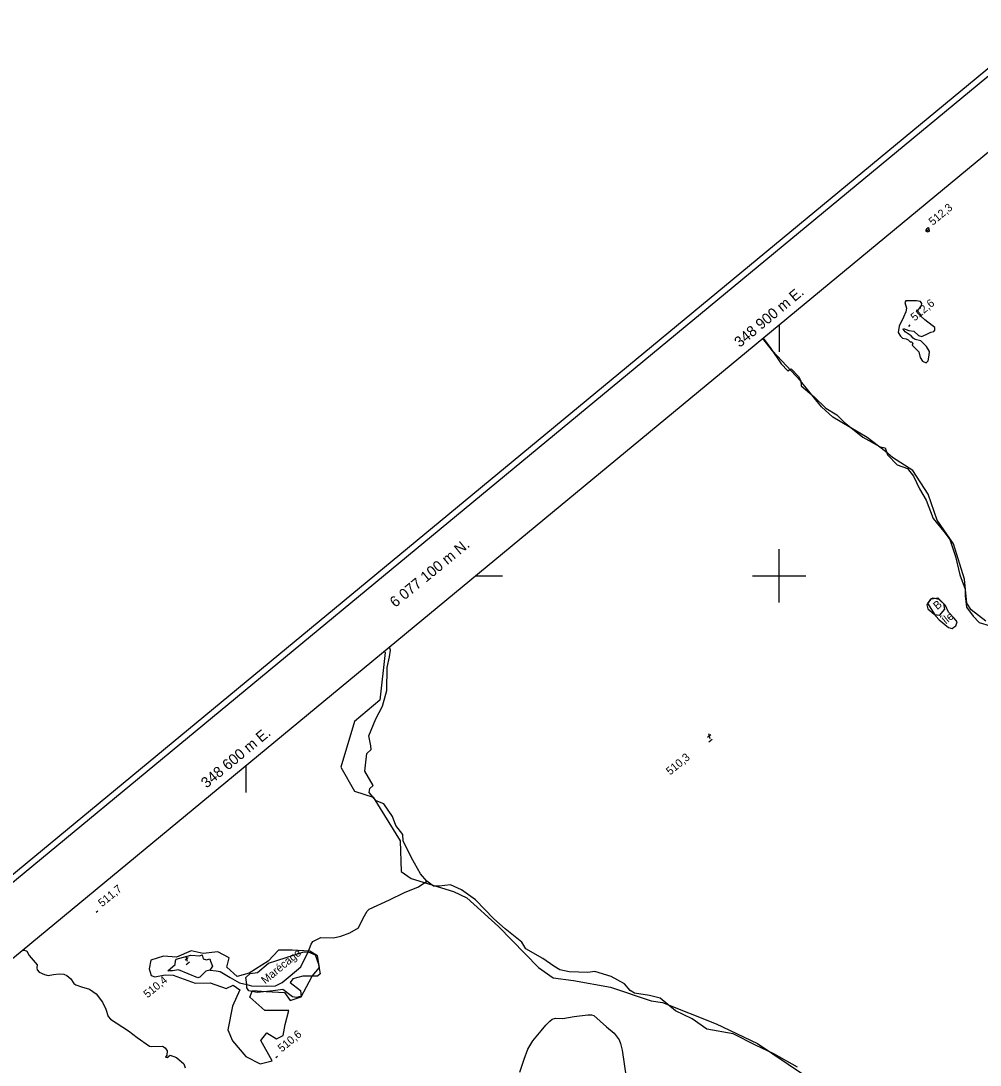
# Model space of a CAD drawing. Extents: x 347059 to 352153, y 6073752 to 6078601.
# Drawn here: x 348473 to 349013, y 6076825 to 6077412 of the extents above; entities that cross this region are included whole.
import ezdxf

# ---------------------------------------------------------------- set-up
doc = ezdxf.new("R2010")
doc.units = 0
for name, color, linetype in [('Level 1', 7, 'Continuous'), ('Level 2', 7, 'Continuous'), ('Level 22', 7, 'Continuous'), ('Level 3', 7, 'Continuous'), ('Level 4', 7, 'Continuous'), ('Level 44', 7, 'Continuous'), ('Level 60', 7, 'Continuous'), ('Level 61', 7, 'Continuous'), ('Level 7', 7, 'Continuous'), ('Level 8', 7, 'Continuous')]:
    doc.layers.add(name, color=color, linetype=linetype)

msp = doc.modelspace()

# ---------------------------------------------------------------- linework, layer by layer
at = {"layer": 'Level 1'}
msp.add_lwpolyline([(348474.58, 6076889.45), (348475.52, 6076889.34), (348476.87, 6076888.89), (348478.22, 6076886.38), (348481.5, 6076882.44), (348482.72, 6076881.18), (348482.51, 6076879.37), (348482.66, 6076878.42), (348483.81, 6076877.1), (348486.7, 6076875.8), (348488.85, 6076875.21), (348491.88, 6076875.66), (348494.98, 6076876.17), (348497.59, 6076875.85), (348499.29, 6076875.14), (348501.49, 6076873.24), (348503.19, 6076870.64), (348504.3, 6076869.83), (348507.51, 6076868.81), (348512.09, 6076867.47), (348515.81, 6076864.81), (348519.38, 6076860.1), (348521.22, 6076856.17), (348522.49, 6076852.15), (348523.83, 6076850.6), (348534.01, 6076844.05), (348538.92, 6076840.28), (348545.9, 6076835.43), (348547.1, 6076835.12), (348553.19, 6076835.35), (348554.7, 6076834.5), (348555.78, 6076832.74), (348555.59, 6076830.43), (348554.84, 6076829.26), (348555.76, 6076828.97), (348557.53, 6076830.35), (348561.11, 6076829.11), (348565.06, 6076825.37), (348565.86, 6076823.22)], dxfattribs=at)
at = {"layer": 'Level 2'}
for points in [[(348982.46, 6077293.93), (348983.6, 6077293.37), (348984.58, 6077293.81), (348984.42, 6077295.27), (348983.97, 6077295.64), (348982.88, 6077294.96), (348982.46, 6077293.93)], [(348975.85, 6077228.81), (348978.66, 6077225.97), (348979.4, 6077222.82), (348980.76, 6077220.72), (348982.83, 6077219.67), (348983.88, 6077220.84), (348984.5, 6077224.07), (348984.69, 6077226.19), (348982.98, 6077228.98), (348979.75, 6077232.15), (348976.64, 6077232.93), (348975.47, 6077233.61), (348974.4, 6077234.9), (348970.97, 6077237.23), (348969.91, 6077238.6), (348969.96, 6077239.09), (348972.96, 6077237.91), (348975.91, 6077237.6), (348978.51, 6077235.1), (348980.34, 6077234.6), (348983.88, 6077236.21), (348985.47, 6077237.01), (348987.01, 6077237.32), (348987.62, 6077238.21), (348987.58, 6077239.53), (348986.14, 6077240.81), (348981.93, 6077243.99), (348979.71, 6077246.04), (348977.91, 6077247.85), (348977.64, 6077248.53), (348980.08, 6077251.93), (348980.34, 6077253.05), (348979.5, 6077254.16), (348977.38, 6077254.64), (348973.94, 6077254.63), (348971.36, 6077254.58), (348970.84, 6077253.76), (348971.68, 6077250.4), (348971.3, 6077248.42), (348970.05, 6077245.49), (348967.5, 6077240.43), (348967.05, 6077236.81), (348968.26, 6077234.81), (348969.42, 6077233.59), (348971.59, 6077233.23), (348972.65, 6077232.68), (348973.8, 6077231.47), (348974.55, 6077231.56), (348975.18, 6077230.8), (348974.95, 6077229.72), (348975.85, 6077228.81)]]:
    msp.add_lwpolyline(points, dxfattribs=at)
at = {"layer": 'Level 22'}
msp.add_lwpolyline([(348754.11, 6076820.73), (348756.65, 6076828.11), (348758.66, 6076833.62), (348761.5, 6076838.4), (348766.13, 6076844), (348768.78, 6076847.12), (348771, 6076849.5), (348772.41, 6076850.61), (348774.17, 6076851.1), (348778.42, 6076851.05), (348784.66, 6076852.13), (348792.43, 6076853.07), (348794.47, 6076852.96), (348795.75, 6076852.6), (348802.86, 6076846.23), (348807.33, 6076842.67), (348810.02, 6076838.9), (348810.87, 6076836.98), (348811.83, 6076833.21), (348814.04, 6076817.7)], dxfattribs=at)
at = {"layer": 'Level 3'}
for p, q in [((348983.09, 6077294.04), (348984.01, 6077294.81)), ((348972.93, 6077240.27), (348973.85, 6077241.04)), ((348859.79, 6077009.14), (348861.6, 6077010.63)), ((348860.25, 6077011.27), (348861.08, 6077008.52)), ((348860.51, 6077006.62), (348862.36, 6077008.15)), ((348515.83, 6076910.79), (348516.75, 6076911.56)), ((348565.82, 6076883.82), (348567.63, 6076885.31)), ((348566.28, 6076885.95), (348567.11, 6076883.2)), ((348566.54, 6076881.3), (348568.39, 6076882.83)), ((348616.9, 6076829.08), (348617.82, 6076829.85))]:
    msp.add_line(p, q, dxfattribs=at)
at = {"layer": 'Level 4'}
for points in [[(348891.08, 6077233.62), (348895.41, 6077227.75), (348901.19, 6077219.15), (348905.01, 6077215.26), (348906.83, 6077216.33), (348910.95, 6077212.08), (348912.28, 6077209.57), (348912.45, 6077206.84), (348919.74, 6077200.58), (348926.3, 6077194.3), (348932.59, 6077190.51), (348936.57, 6077186.45), (348947.18, 6077177.99), (348956.91, 6077172.41), (348959.66, 6077171.99), (348960.93, 6077167.93), (348966.48, 6077162.32), (348972.26, 6077160.23), (348975.73, 6077156.05), (348978.93, 6077148.93), (348982.85, 6077142.57), (348986.75, 6077132.27), (348992.7, 6077124.9), (348996.05, 6077120.32), (348999.19, 6077110.75), (349001.69, 6077100.5), (349004.64, 6077092.43), (349004.71, 6077088.72), (349005.43, 6077082.25), (349009.23, 6077077.3), (349012.58, 6077073.63), (349018.8, 6077071.91)], [(348983.71, 6077081.32), (348987.28, 6077078.36), (348988.12, 6077077.18), (348990.11, 6077075.23), (348995.36, 6077070.97), (348997.35, 6077070.3), (348998.35, 6077070.99), (348999.54, 6077071.91), (349000.19, 6077074.1), (348998.54, 6077076.19), (348995.37, 6077079.55), (348993.58, 6077083.25), (348990.16, 6077086.56), (348986.51, 6077087.34), (348985.16, 6077086.89), (348983.15, 6077083.71), (348983.71, 6077081.32)], [(348833.12, 6076862.33), (348827.13, 6076863.94), (348818.73, 6076865.19), (348816.16, 6076866.65), (348812.99, 6076870.46), (348805.59, 6076874.65), (348796.27, 6076877.38), (348792.46, 6076876.9), (348781.94, 6076877.28), (348776.71, 6076878.32), (348773.21, 6076880.36), (348767.05, 6076884.69), (348757.48, 6076890.22), (348755.35, 6076893.86), (348745.88, 6076901.44), (348739.51, 6076907.1), (348729.23, 6076917.63), (348721.38, 6076923.26), (348715.08, 6076926.12), (348708.88, 6076925.45), (348705.51, 6076925.35), (348701.83, 6076928.14), (348698.35, 6076932.31), (348693.26, 6076941.31), (348688.45, 6076950.86), (348688.29, 6076954.48), (348684.48, 6076959.59), (348682.55, 6076964.61), (348677.62, 6076971.79), (348673.42, 6076973.4), (348669.41, 6076978.03), (348669.86, 6076980.37), (348671.74, 6076982.09), (348666.95, 6076990), (348667.34, 6076993.5), (348668.08, 6077000), (348670.49, 6077002.17), (348670.27, 6077004.24), (348669.13, 6077009.93), (348673.1, 6077019.43), (348676.85, 6077026.65), (348679.44, 6077035.45), (348679.53, 6077048.35), (348680.88, 6077054.31), (348681.38, 6077058.04), (348680.84, 6077059.89)], [(348600.52, 6076870), (348603.17, 6076869.37), (348611.63, 6076869.14), (348616.74, 6076869.42), (348620.38, 6076871.18), (348625.02, 6076874.99), (348630.99, 6076879.99), (348635.05, 6076888.51), (348635.88, 6076890.25), (348636.73, 6076892.84), (348637.8, 6076894.35), (348642.3, 6076896.52), (348649.36, 6076896.26), (348653.46, 6076897.2), (348658.51, 6076899.16), (348663.34, 6076901.93), (348666, 6076907.39), (348668.24, 6076911.37), (348669.49, 6076912.49), (348680.89, 6076917.74), (348689.25, 6076921.86), (348697.15, 6076925.01), (348701.83, 6076928.14)], [(348556.21, 6076877.73), (348560.25, 6076881.26), (348560.48, 6076883.42), (348560.76, 6076884.25), (348565, 6076885.39), (348569.04, 6076886.58), (348574.09, 6076886.21), (348575.54, 6076886.82), (348576.02, 6076884.44), (348577.98, 6076883.89), (348579.81, 6076884.59), (348580.18, 6076883.24), (348581.36, 6076880.39), (348579.86, 6076878.23), (348577.51, 6076877.62), (348574.06, 6076874.28), (348572.96, 6076873.88), (348562.15, 6076878.26), (348558.76, 6076877.83), (348556.21, 6076877.73)], [(348579.78, 6076878.2), (348583.27, 6076877.81), (348585.65, 6076877.39), (348591.21, 6076873.98), (348596.51, 6076870.96), (348600.52, 6076870)], [(348910.46, 6076823.5), (348897.02, 6076831.18), (348886.82, 6076835.87), (348874.17, 6076842.41), (348859.44, 6076844.97), (348851.04, 6076850.72), (348841.72, 6076855.25), (348833.12, 6076862.33)]]:
    msp.add_lwpolyline(points, dxfattribs=at)
at = {"layer": 'Level 44'}
for points in [[(349016.33, 6077074.39), (349008.01, 6077080.81), (349005.65, 6077084.55), (349004.35, 6077098.05), (348998.23, 6077117.89), (348988.98, 6077131.21), (348983.85, 6077145.89), (348975.18, 6077159.24), (348963.81, 6077166.45), (348959.95, 6077169.84), (348949.62, 6077177.77), (348930.29, 6077189.16), (348923.94, 6077195), (348912.01, 6077209.57), (348896.34, 6077226.47), (348890.93, 6077233.5)], [(348987.9, 6077078.02), (348983.67, 6077084.56), (348985.69, 6077087), (348989.26, 6077087.58), (348992.56, 6077084.33), (348993.09, 6077081.16), (348990.15, 6077077.65), (348987.9, 6077078.02)], [(348677.82, 6077057.39), (348678.39, 6077056.79), (348675.5, 6077029.96), (348661.17, 6077017.97), (348653.47, 6076992.25), (348661.11, 6076978.76), (348671.63, 6076975.51), (348686.78, 6076950.85), (348687.37, 6076933.58), (348693.07, 6076929.62), (348716.81, 6076922.4), (348724.34, 6076918.77), (348742.2, 6076902.73), (348764.67, 6076879.74), (348772.96, 6076873.75), (348784.28, 6076872.4), (348805.18, 6076868.55), (348828.03, 6076860.93), (348834.48, 6076860.02), (348864.6, 6076847.97), (348887.93, 6076836.88), (348913.79, 6076819.49)], [(348559.19, 6076875.25), (348571.5, 6076870.78), (348579.87, 6076871.01), (348588.93, 6076867.9), (348592.95, 6076869.75), (348596.64, 6076867.13), (348592.56, 6076857.99), (348589.9, 6076844.62), (348592.54, 6076838.41), (348600.1, 6076829.53), (348608.01, 6076825.46), (348614.78, 6076827.07), (348608.51, 6076838.53), (348611.84, 6076842.81), (348617.36, 6076839.45), (348621.06, 6076841.49), (348622.09, 6076847.63), (348624.19, 6076855.55), (348610.67, 6076855.37), (348602.25, 6076862.93), (348603.73, 6076866.73), (348611.46, 6076866.12), (348621.81, 6076865.6), (348624.93, 6076861.14), (348631.17, 6076863.2), (348635.69, 6076871.64), (348637.35, 6076874.69), (348641.48, 6076879.64), (348640.42, 6076886.13), (348636, 6076888.91), (348626.05, 6076889.31), (348618.44, 6076889.42), (348612.65, 6076883.22), (348601.97, 6076876.4), (348595.09, 6076874.56), (348589.26, 6076879.92), (348590.7, 6076885.04), (348584.21, 6076888.49), (348576.01, 6076887.51), (348569.26, 6076888.94), (348561.08, 6076885.41), (348553.68, 6076886), (348546.6, 6076883.85), (348545.59, 6076878.94), (348546.74, 6076875.23), (348548.8, 6076874.38), (348554.72, 6076875.57), (348559.19, 6076875.25)]]:
    msp.add_lwpolyline(points, dxfattribs=at)
at = {"layer": 'Level 60'}
for p, q in [((348900, 6077240.99), (348900, 6077225.99)), ((348729.38, 6077100), (348744.38, 6077100)), ((348600, 6076993.09), (348600, 6076978.09))]:
    msp.add_line(p, q, dxfattribs=at)
for points in [[(350488.49, 6078600.77), (347058.77, 6075766.69)], [(350488.06, 6078596.06), (347063.49, 6075766.23)]]:
    msp.add_lwpolyline(points, dxfattribs=at)
msp.add_lwpolyline([(347109.95, 6075761.81), (348728.53, 6073803.05), (351407.22, 6076016.53), (349788.63, 6077975.29)], close=True, dxfattribs=at)
at = {"layer": 'Level 61'}
for p, q in [((348900, 6077085), (348900, 6077115)), ((348885, 6077100), (348915, 6077100))]:
    msp.add_line(p, q, dxfattribs=at)
at = {"layer": 'Level 7'}
msp.add_lwpolyline([(348600.07, 6076874.08), (348602.4, 6076876.33), (348606.54, 6076876.78), (348612.75, 6076882.13), (348617.39, 6076883.59), (348632.07, 6076888.34), (348635.05, 6076888.51), (348639, 6076886.84), (348640.79, 6076882.16), (348641.88, 6076876), (348640.38, 6076874.74), (348632.1, 6076874.74), (348626.48, 6076873.2), (348624.99, 6076871.2), (348630.82, 6076866.74), (348631.11, 6076863.52), (348628.51, 6076862.85), (348626.32, 6076863.13), (348620.87, 6076867.31), (348615.48, 6076866.56), (348606.47, 6076865.65), (348601.63, 6076866.58), (348600.63, 6076868.15), (348600.52, 6076870), (348600.07, 6076874.08)], dxfattribs=at)

# ---------------------------------------------------------------- texts
at = {"layer": 'Level 3'}
for s, rotation, p in [('512,3', 39.62, (348986.45, 6077296.76)), ('512,6', 39.62, (348976.29, 6077242.98)), ('  510,3', 39.57, (348836.12, 6076985.45)), ('511,7', 39.62, (348519.19, 6076913.5)), ('  510,4', 39.57, (348542.14, 6076860.11)), ('510,6', 39.62, (348620.26, 6076831.8))]:
    msp.add_text(s, height=4.5, rotation=rotation, dxfattribs=at).set_placement(p)
at = {"layer": 'Level 44'}
msp.add_text('B', height=4.5, rotation=39.568, dxfattribs=at).set_placement((348988.99, 6077080.6))
at = {"layer": 'Level 61'}
for s, height, rotation, p in [('348 900 m E. ', 6, 39.81296, (348877.9, 6077228.11)), ('6 077 100 m N.', 6.0001, 39.36439, (348684.08, 6077081.85)), ('348 600 m E. ', 6, 39.81296, (348577.9, 6076980.21))]:
    msp.add_text(s, height=height, rotation=rotation, dxfattribs=at).set_placement(p)
at = {"layer": 'Level 7'}
msp.add_text('Marécage', height=4.5, rotation=39.568, dxfattribs=at).set_placement((348610.93, 6076870.08))
at = {"layer": 'Level 8'}
msp.add_text('Île', height=4.5, rotation=39.568, dxfattribs=at).set_placement((348993.79, 6077072.46))

doc.saveas('drawing.dxf')
